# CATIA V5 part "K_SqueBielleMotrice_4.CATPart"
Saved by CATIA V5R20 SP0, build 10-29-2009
Part number: Squelette_bielle_motrice_4
Publications: "Droite.1", "Droite.2"
Bounding box of the stored display mesh (mm): x -180 to -90, y -40 to 0, z -50 to -50
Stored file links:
  G:\Khaled_CFAO_2011\ST2M\ST2M_GR2\jcoetard\Khaled\CAD_CATIA\K_SqueBielleMotrice_4.CATPart
  G:\Khaled_CFAO_2011\ST2M\ST2M_GR2\jcoetard\Khaled\CAD_CATIA\K_Squelette.CATProduct
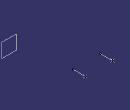
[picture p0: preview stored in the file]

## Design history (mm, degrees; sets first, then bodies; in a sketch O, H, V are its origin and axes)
Set1
  Plane1 "Plan_bielle_motrice_02": linked copy from another document
  Point1 "Point.12": linked copy from another document
  Point2 "Point.11": linked copy from another document
Set2 "Set géométrique"
  Line1: type Normal, RefPoint Point1, RefSkin Plane1, Start 0, End 40
  Line2: type Normal, RefPoint Point2, RefSkin Plane1, Start 0, End 40
Body1 (main body)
